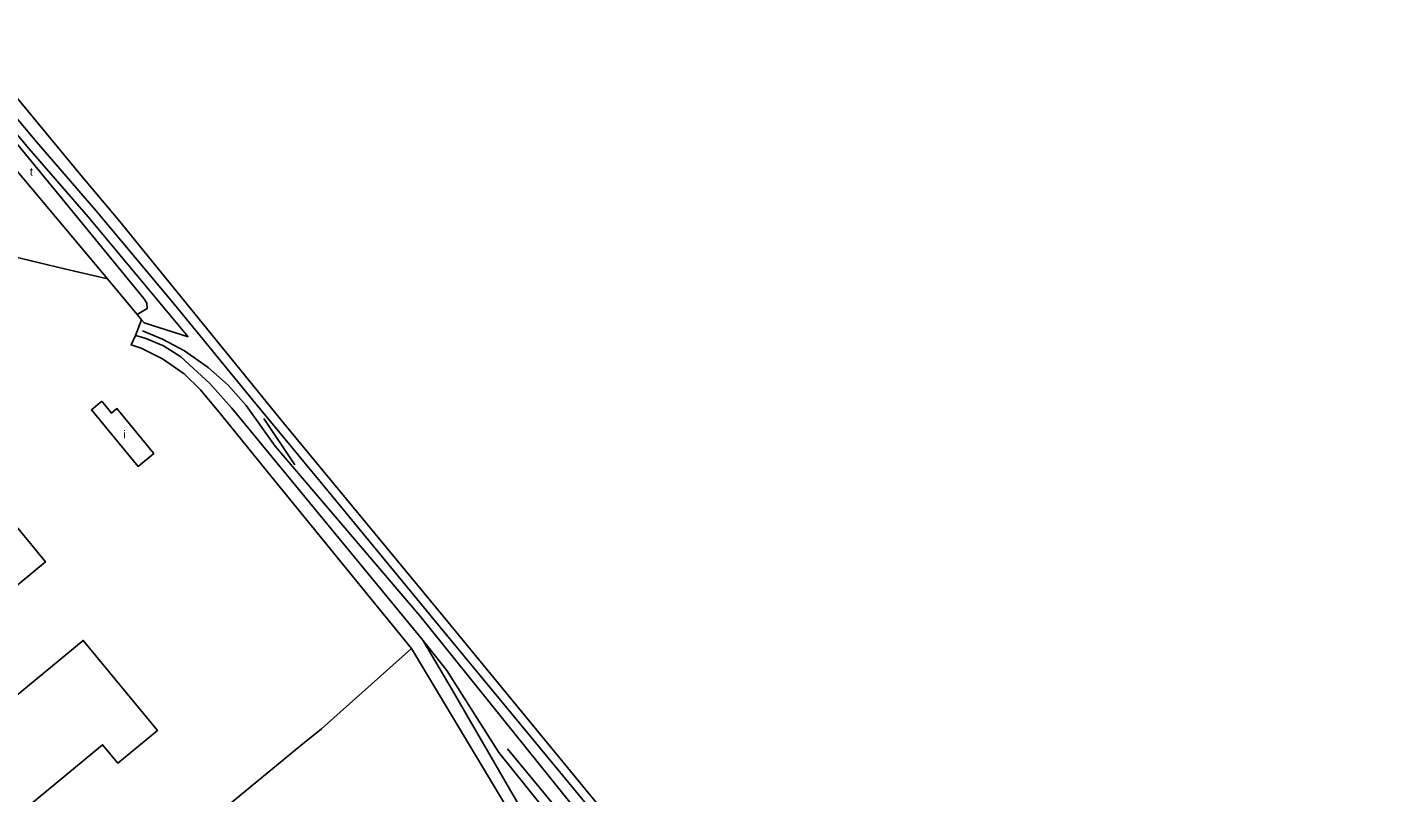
# Model space of a CAD drawing. Extents: x 156097 to 158136, y 385644 to 388348.
# Drawn here: x 157432 to 158115, y 387162 to 387544 of the extents above; entities that cross this region are included whole.
import ezdxf

# ---------------------------------------------------------------- set-up
doc = ezdxf.new("R2010")
doc.units = 0
for name, color, linetype in [('BLT_Basislijn', 7, 'Continuous'), ('BLT_Bebouwing', 7, 'Continuous'), ('BLT_Centroide', 7, 'Continuous'), ('BLT_Spoorlijn', 7, 'Continuous')]:
    doc.layers.add(name, color=color, linetype=linetype)

msp = doc.modelspace()

# ---------------------------------------------------------------- linework, layer by layer
at = {"layer": 'BLT_Basislijn'}
for p, q in [((157425.71, 387474.17), (157472.38, 387418.46)), ((157472.38, 387418.46), (157487.31, 387400.64)), ((157489.5, 387398.02), (157486.36, 387390.22)), ((157487.31, 387400.64), (157489.5, 387398.02)), ((157518.83, 387363.01), (157529.52, 387350.25)), ((157529.52, 387350.25), (157552.41, 387322.15)), ((157552.41, 387322.15), (157611.02, 387250.24)), ((157611.02, 387250.24), (157611.21, 387250)), ((157611.21, 387250), (157624.27, 387233.99))]:
    msp.add_line(p, q, dxfattribs=at)
for points in [[(157512.73, 387389.59), (157462.83, 387449.43), (157433.16, 387483.59), (157400.94, 387521.92), (157384.41, 387541.74)], [(157392.46, 387527.53), (157393.05, 387527.27), (157448.29, 387460.32), (157490.66, 387408.7), (157492.08, 387406.32), (157492.29, 387403.67), (157487.31, 387400.64)], [(157450.99, 387423.54), (157417.45, 387431.51), (157413.24, 387432.85)], [(157472.38, 387418.46), (157450.99, 387423.54)], [(157489.5, 387398.02), (157490.81, 387396.45), (157512.73, 387389.59)], [(157486.36, 387390.22), (157484.31, 387385.53), (157489.2, 387383.86), (157499.94, 387378.5), (157510.76, 387371.01), (157518.83, 387363.01)], [(157500.39, 387385.02), (157491.24, 387388.8), (157486.36, 387390.22)], [(157500.39, 387385.02), (157509.05, 387379.56), (157523.63, 387366.19), (157534.5, 387353.88), (157630.07, 387238.05)], [(157624.27, 387233.99), (157579.43, 387193.83), (157569.12, 387185.66), (157526.77, 387150.7)], [(157711.8, 387103.12), (157679.82, 387141.56), (157624.27, 387233.99)], [(157630.07, 387238.05), (157644.68, 387213.21), (157685.39, 387142.92), (157751.06, 387063.19)], [(157630.07, 387238.05), (157641.94, 387222.97), (157667.98, 387181.96), (157701.49, 387140.38), (157739.89, 387082.26), (157751.06, 387063.19)]]:
    msp.add_lwpolyline(points, dxfattribs=at)
at = {"layer": 'BLT_Bebouwing'}
for points in [[(157469.58, 387357.33), (157464.41, 387353.08), (157487.69, 387324.85), (157495.56, 387331.31), (157477.11, 387353.7), (157474.43, 387351.43)], [(157330.32, 387055.02), (157369.92, 387087.72), (157362.29, 387096.97), (157371.11, 387104.35), (157372.36, 387102.86), (157374.45, 387102.96), (157376.12, 387102.26), (157377.56, 387100.99), (157378.05, 387099.5), (157384.37, 387104.72), (157379.21, 387110.93), (157469.96, 387185.87), (157477.56, 387176.69), (157497.38, 387193.06), (157460.35, 387237.99), (157354.89, 387150.97), (157319.99, 387193.25), (157413.54, 387270.58), (157422.05, 387261.11), (157441.45, 387277.16), (157403.93, 387322.7), (157252.98, 387198.06), (157197.06, 387265.8), (157172.83, 387245.77)]]:
    msp.add_lwpolyline(points, close=True, dxfattribs=at)
at = {"layer": 'BLT_Spoorlijn'}
for p, q in [((157459.06, 387470.25), (157477.74, 387448.12)), ((157477.74, 387448.12), (157560.2, 387346.8)), ((157489.91, 387392.45), (157500, 387388.33)), ((157541.72, 387355.17), (157556.17, 387334.87)), ((157556.17, 387334.87), (157628.61, 387250))]:
    msp.add_line(p, q, dxfattribs=at)
for points in [[(157388.99, 387544.06), (157404.77, 387525.13), (157436.96, 387486.84), (157466.64, 387452.67), (157505.83, 387405.66)], [(157400.66, 387540.88), (157459.06, 387470.25)], [(158114.59, 386668.56), (158068.11, 386724.83), (158009.23, 386796.18), (157930.12, 386891.81), (157831.9, 387010.77), (157721.95, 387143.82), (157638.68, 387244.6), (157584.2, 387310.67), (157545.08, 387357.98), (157505.83, 387405.66)], [(157500, 387388.33), (157510.89, 387382.6), (157522.77, 387374.15), (157532.76, 387365.33), (157541.72, 387355.17)], [(157566.05, 387325.65), (157550.62, 387348.73)], [(157560.2, 387346.8), (157640.11, 387250)], [(157628.61, 387250), (157717.05, 387140.23), (157834.82, 386997.8), (157942.16, 386868.13), (158014.56, 386779.96), (158077.18, 386704.5), (158109.93, 386664.79)], [(157640.11, 387250), (157671.68, 387211.75)], [(157671.68, 387211.75), (157726.79, 387144.7)], [(157672.34, 387183.89), (157707.12, 387141.67), (157740.15, 387090), (157808.39, 387004.56), (157865.24, 386936.61), (157883.2, 386917.03), (157930.67, 386872.31), (157998.86, 386790.82), (158030.8, 386749.92)]]:
    msp.add_lwpolyline(points, dxfattribs=at)

# ---------------------------------------------------------------- texts
at = {"layer": 'BLT_Centroide'}
for s, p in [('t', (157433.65, 387470.02)), ('i', (157480.35, 387338.78))]:
    msp.add_text(s, height=4, dxfattribs=at).set_placement(p)

doc.saveas('drawing.dxf')
